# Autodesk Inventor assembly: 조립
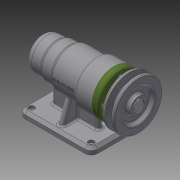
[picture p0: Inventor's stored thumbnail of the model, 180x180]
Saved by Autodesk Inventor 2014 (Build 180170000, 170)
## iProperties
Created: 2016-06
Part Number: 조립
Document SubType Name: Assembly
Designer: L6
Author: L6
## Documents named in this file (12)
- C:\Users\L6\Desktop\460608V1001\조립.iam
- C:\Users\L6\Desktop\460608V1001\본체.ipt
- C:\Users\L6\Desktop\460608V1001\축.ipt
- C:\Users\L6\Desktop\460608V1001\베어링 6004.ipt
- C:\Users\L6\Desktop\460608V1001\어댑터슬리브.ipt
- C:\Users\L6\Desktop\460608V1001\베어링 51202.ipt
- C:\Users\L6\Desktop\460608V1001\볼트 M4 x 12.ipt
- C:\Users\L6\Desktop\460608V1001\키 5 x 5 x 16.ipt
- C:\Users\L6\Desktop\460608V1001\커버.ipt
- C:\Users\L6\Desktop\460608V1001\오일 실.ipt
- C:\Users\L6\Desktop\460608V1001\V벨트풀리.ipt
- C:\Users\L6\Desktop\460608V1001\멈춤나사 M3x8.ipt
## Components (6 placed, 2 different names)
1. ISO 4762 M4 x 12:1 — 각도:3
2. V벨트풀리:1 — 각도:5
3. ISO 4762 M4 x 12:2 — 각도:4
4. ISO 4762 M4 x 12:3
5. ISO 4762 M4 x 12:4
6. ISO 4762 M4 x 12:5
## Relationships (3: Angle 3)
- 각도:3 [Angle]: ISO 4762 M4 x 12:1
- 각도:4 [Angle]: ISO 4762 M4 x 12:2
- 각도:5 [Angle]: V벨트풀리:1
